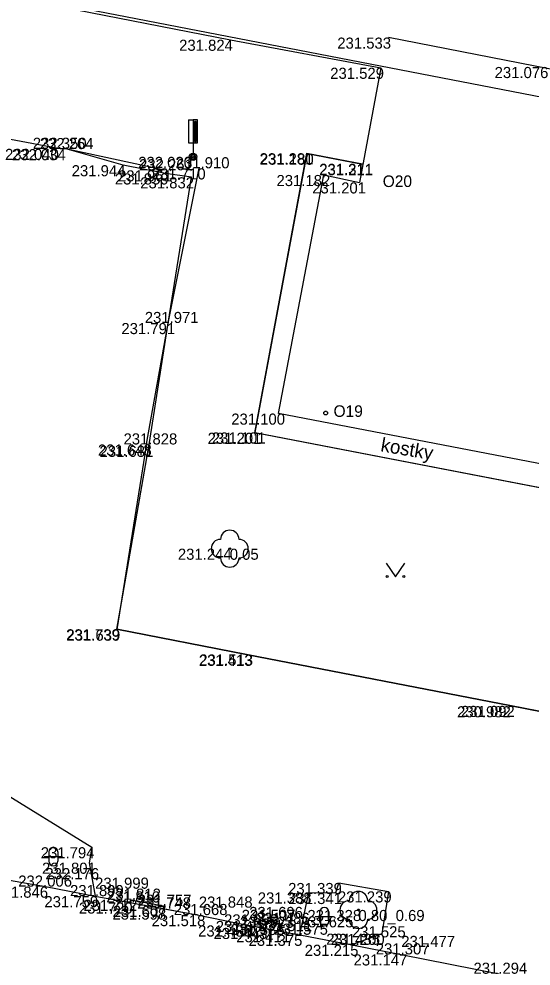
# Model space of a CAD drawing. Extents: x -599516 to -599132, y -1163668 to -1163119.
# Drawn here: x -599461.53 to -599447.72, y -1163158.24 to -1163132.67 of the extents above; entities that cross this region are included whole.
import ezdxf

# ---------------------------------------------------------------- set-up
doc = ezdxf.new("R2010")
doc.units = 0
for name, color, linetype in [('_ZEMERENI OBLAST', 7, 'Continuous'), ('Bod-oznac1', 7, 'Continuous'), ('Bod-oznac2', 7, 'Continuous'), ('Bod-oznac3', 7, 'Continuous'), ('Bod-vyska1', 7, 'Continuous'), ('Bod-vyska2', 7, 'Continuous'), ('Bod-vyska3', 7, 'Continuous'), ('Z_budovy-obvod', 7, 'Continuous'), ('Z_cela-hrobu-dolni-linie', 7, 'Continuous'), ('Z_cela-hrobu-horni-linie', 7, 'Continuous'), ('Z_destove-svody-cislo-foto', 7, 'Continuous'), ('Z_destove-svody-obvod', 7, 'Continuous'), ('Z_komunikace', 7, 'Continuous'), ('Z_kultury-znacky', 7, 'Continuous'), ('Z_nove-stromy-prumer-kmene', 7, 'Continuous'), ('Z_obvod-kmene-spodek-ve-vysce1_2m', 7, 'Continuous'), ('Z_popis-budov-povrchu', 7, 'Continuous'), ('Z_stromy-kere', 7, 'Continuous'), ('Z_stromy-nove-vysazene', 7, 'Continuous'), ('Z_vol-lin-obrubnik', 7, 'Continuous'), ('Z_zdi-ohradni', 7, 'Continuous'), ('Z_znacky-ostatni-orientacni-sloupek', 7, 'Continuous'), ('Z_zpevnene-plochy', 7, 'Continuous')]:
    doc.layers.add(name, color=color, linetype=linetype)

msp = doc.modelspace()

# ---------------------------------------------------------------- linework, layer by layer
at = {"layer": '_ZEMERENI OBLAST'}
msp.add_lwpolyline([(-599246.21, -1163173.61), (-599310.76, -1163161.2), (-599382.471, -1163147.382), (-599418.511, -1163140.298), (-599415.805, -1163126.425), (-599441.73, -1163121.594), (-599445.004, -1163135.25), (-599483.712, -1163127.751), (-599506.25, -1163123.345), (-599510.771, -1163146.476), (-599502.636, -1163301.975), (-599510.038, -1163302.355), (-599510.12, -1163309.17), (-599515.16, -1163309.664), (-599511.204, -1163380.278), (-599506.35, -1163380.56), (-599506.01, -1163391.1), (-599497.946, -1163390.674), (-599491.96, -1163502.01)], dxfattribs=at)
at = {"layer": 'Bod-oznac1'}
for p, q in [((-599451.567, -1163133.168), (-599451.567, -1163133.168)), ((-599455.824, -1163133.226), (-599455.824, -1163133.226)), ((-599451.77, -1163133.983), (-599451.77, -1163133.983)), ((-599460.421, -1163136.173), (-599460.421, -1163136.173)), ((-599460.233, -1163136.181), (-599460.233, -1163136.181)), ((-599456.838, -1163136.389), (-599456.838, -1163136.389)), ((-599453.768, -1163136.291), (-599453.768, -1163136.291)), ((-599453.76, -1163136.303), (-599453.76, -1163136.303)), ((-599458.723, -1163136.614), (-599458.723, -1163136.614)), ((-599457.611, -1163136.753), (-599457.611, -1163136.753)), ((-599456.674, -1163136.699), (-599456.674, -1163136.699)), ((-599452.263, -1163136.586), (-599452.263, -1163136.586)), ((-599452.261, -1163136.576), (-599452.261, -1163136.576)), ((-599457.582, -1163136.836), (-599457.582, -1163136.836)), ((-599456.883, -1163136.941), (-599456.883, -1163136.941)), ((-599453.312, -1163136.879), (-599453.312, -1163136.879)), ((-599452.349, -1163137.078), (-599452.349, -1163137.078)), ((-599457.507, -1163140.877), (-599457.507, -1163140.877)), ((-599454.536, -1163143.322), (-599454.536, -1163143.322)), ((-599455.172, -1163143.84), (-599455.172, -1163143.84)), ((-599455.16, -1163143.832), (-599455.16, -1163143.832)), ((-599458.099, -1163144.192), (-599458.099, -1163144.192)), ((-599458.024, -1163144.157), (-599458.024, -1163144.157)), ((-599455.847, -1163146.971), (-599455.847, -1163146.971)), ((-599458.897, -1163149.157), (-599458.897, -1163149.157)), ((-599458.895, -1163149.147), (-599458.895, -1163149.147)), ((-599455.397, -1163149.836), (-599455.397, -1163149.836)), ((-599455.395, -1163149.826), (-599455.395, -1163149.826)), ((-599448.245, -1163151.226), (-599448.245, -1163151.226)), ((-599448.243, -1163151.216), (-599448.243, -1163151.216)), ((-599459.568, -1163155.034), (-599459.568, -1163155.034)), ((-599459.64, -1163155.451), (-599459.64, -1163155.451)), ((-599460.821, -1163156.098), (-599460.821, -1163156.098)), ((-599452.906, -1163155.999), (-599452.906, -1163155.999)), ((-599459.48, -1163156.355), (-599459.48, -1163156.355)), ((-599458.519, -1163156.452), (-599458.519, -1163156.452)), ((-599453.713, -1163156.254), (-599453.713, -1163156.254)), ((-599452.984, -1163156.269), (-599452.984, -1163156.269)), ((-599451.563, -1163156.226), (-599451.563, -1163156.226)), ((-599458.54, -1163156.526), (-599458.54, -1163156.526)), ((-599457.647, -1163156.689), (-599457.647, -1163156.689)), ((-599457.639, -1163156.615), (-599457.639, -1163156.615)), ((-599456.681, -1163156.866), (-599456.681, -1163156.866)), ((-599452.374, -1163156.728), (-599452.374, -1163156.728)), ((-599455.323, -1163157.146), (-599455.323, -1163157.146)), ((-599454.884, -1163157.212), (-599454.884, -1163157.212)), ((-599454.836, -1163157.024), (-599454.836, -1163157.024)), ((-599454.452, -1163157.105), (-599454.452, -1163157.105)), ((-599454.489, -1163157.301), (-599454.489, -1163157.301)), ((-599453.959, -1163157.398), (-599453.959, -1163157.398)), ((-599451.746, -1163157.373), (-599451.746, -1163157.373)), ((-599452.55, -1163157.668), (-599452.55, -1163157.668)), ((-599451.218, -1163157.928), (-599451.218, -1163157.928))]:
    msp.add_line(p, q, dxfattribs=at)
at = {"layer": 'Bod-oznac2'}
for p, q in [((-599460.421, -1163136.173), (-599460.421, -1163136.173)), ((-599460.233, -1163136.181), (-599460.233, -1163136.181)), ((-599457.611, -1163136.753), (-599457.611, -1163136.753)), ((-599456.674, -1163136.699), (-599456.674, -1163136.699)), ((-599457.507, -1163140.877), (-599457.507, -1163140.877)), ((-599458.024, -1163144.157), (-599458.024, -1163144.157)), ((-599460.821, -1163156.098), (-599460.821, -1163156.098)), ((-599459.48, -1163156.355), (-599459.48, -1163156.355)), ((-599458.519, -1163156.452), (-599458.519, -1163156.452)), ((-599458.54, -1163156.526), (-599458.54, -1163156.526)), ((-599457.647, -1163156.689), (-599457.647, -1163156.689)), ((-599457.639, -1163156.615), (-599457.639, -1163156.615)), ((-599456.681, -1163156.866), (-599456.681, -1163156.866)), ((-599455.323, -1163157.146), (-599455.323, -1163157.146)), ((-599454.884, -1163157.212), (-599454.884, -1163157.212)), ((-599454.836, -1163157.024), (-599454.836, -1163157.024)), ((-599454.452, -1163157.105), (-599454.452, -1163157.105)), ((-599454.489, -1163157.301), (-599454.489, -1163157.301)), ((-599453.959, -1163157.398), (-599453.959, -1163157.398)), ((-599452.55, -1163157.668), (-599452.55, -1163157.668)), ((-599451.218, -1163157.928), (-599451.218, -1163157.928))]:
    msp.add_line(p, q, dxfattribs=at)
at = {"layer": 'Bod-oznac3'}
for p, q in [((-599460.821, -1163156.098), (-599460.821, -1163156.098)), ((-599459.48, -1163156.355), (-599459.48, -1163156.355)), ((-599456.681, -1163156.866), (-599456.681, -1163156.866)), ((-599455.323, -1163157.146), (-599455.323, -1163157.146)), ((-599453.959, -1163157.398), (-599453.959, -1163157.398)), ((-599452.55, -1163157.668), (-599452.55, -1163157.668)), ((-599451.218, -1163157.928), (-599451.218, -1163157.928))]:
    msp.add_line(p, q, dxfattribs=at)
at = {"layer": 'Z_budovy-obvod'}
msp.add_lwpolyline([(-599441.599, -1163138.884), (-599440.699, -1163139.073), (-599440.942, -1163140.393), (-599440.942, -1163140.393), (-599441.039, -1163140.899), (-599441.038, -1163140.9), (-599441.617, -1163143.927), (-599441.618, -1163143.927), (-599441.719, -1163144.457), (-599441.719, -1163144.457), (-599441.951, -1163145.746), (-599454.536, -1163143.322), (-599453.312, -1163136.879), (-599452.349, -1163137.078)], dxfattribs=at)
at = {"layer": 'Z_cela-hrobu-dolni-linie'}
for p, q in [((-599458.54, -1163156.526), (-599457.647, -1163156.689)), ((-599453.959, -1163157.398), (-599452.55, -1163157.668))]:
    msp.add_line(p, q, dxfattribs=at)
for points in [[(-599457.611, -1163136.753), (-599460.233, -1163136.181)], [(-599466.352, -1163155.068), (-599465.003, -1163155.358), (-599463.695, -1163155.552), (-599462.314, -1163155.831), (-599460.821, -1163156.098), (-599459.48, -1163156.355)]]:
    msp.add_lwpolyline(points, dxfattribs=at)
at = {"layer": 'Z_cela-hrobu-horni-linie'}
for points in [[(-599460.421, -1163136.173), (-599463.111, -1163135.666), (-599463.111, -1163135.666), (-599464.381, -1163135.363), (-599464.381, -1163135.363), (-599466.992, -1163134.883), (-599466.992, -1163134.883), (-599469.676, -1163134.264), (-599469.676, -1163134.264), (-599470.948, -1163133.966), (-599470.948, -1163133.966), (-599472.276, -1163133.77), (-599472.276, -1163133.77), (-599474.675, -1163133.29), (-599474.675, -1163133.29), (-599475.999, -1163133.032), (-599476.509, -1163133.063), (-599476.548, -1163133.289), (-599477.916, -1163133.033), (-599477.892, -1163132.869)], [(-599457.611, -1163136.753), (-599460.233, -1163136.181)], [(-599462.314, -1163155.831), (-599460.821, -1163156.098), (-599460.821, -1163156.098), (-599459.48, -1163156.355), (-599459.48, -1163156.355), (-599456.681, -1163156.866), (-599456.681, -1163156.866), (-599455.323, -1163157.146), (-599455.323, -1163157.146), (-599453.959, -1163157.398), (-599453.959, -1163157.398), (-599452.55, -1163157.668), (-599452.55, -1163157.668), (-599451.218, -1163157.928), (-599451.218, -1163157.928), (-599448.581, -1163158.452)]]:
    msp.add_lwpolyline(points, dxfattribs=at)
at = {"layer": 'Z_destove-svody-obvod'}
msp.add_circle((-599453.259, -1163143.308), 0.05, dxfattribs=at)
at = {"layer": 'Z_komunikace'}
msp.add_line((-599458.099, -1163144.192), (-599458.897, -1163149.157), dxfattribs=at)
for points in [[(-599458.099, -1163144.192), (-599457.507, -1163140.877), (-599456.883, -1163136.941), (-599457.582, -1163136.836), (-599458.723, -1163136.614), (-599460.233, -1163136.181), (-599460.421, -1163136.173), (-599463.111, -1163135.666), (-599464.381, -1163135.363), (-599466.992, -1163134.883), (-599469.676, -1163134.264), (-599470.31, -1163134.116), (-599470.376, -1163134.855), (-599470.327, -1163135.489), (-599471.713, -1163135.45), (-599472.484, -1163135.263), (-599472.617, -1163134.911)], [(-599439.001, -1163153.032), (-599448.245, -1163151.226), (-599455.397, -1163149.836), (-599458.897, -1163149.157)], [(-599462.138, -1163153.45), (-599459.568, -1163155.034), (-599459.64, -1163155.451), (-599459.48, -1163156.355), (-599458.54, -1163156.526), (-599458.519, -1163156.452), (-599457.639, -1163156.615), (-599457.647, -1163156.689), (-599456.681, -1163156.866), (-599455.323, -1163157.146), (-599454.884, -1163157.212), (-599454.836, -1163157.024), (-599454.452, -1163157.105), (-599454.489, -1163157.301), (-599453.959, -1163157.398), (-599453.713, -1163156.254), (-599452.984, -1163156.269), (-599452.906, -1163155.999), (-599451.563, -1163156.226), (-599451.746, -1163157.373), (-599452.55, -1163157.668), (-599451.218, -1163157.928), (-599448.581, -1163158.452)]]:
    msp.add_lwpolyline(points, dxfattribs=at)
at = {"layer": 'Z_kultury-znacky'}
for p, q in [((-599451.622, -1163147.36), (-599451.372, -1163147.735)), ((-599451.372, -1163147.735), (-599451.122, -1163147.36)), ((-599460.733, -1163155.161), (-599460.733, -1163155.411)), ((-599460.483, -1163155.161), (-599460.483, -1163155.411)), ((-599460.858, -1163155.286), (-599460.358, -1163155.286)), ((-599453.546, -1163156.908), (-599453.046, -1163156.908)), ((-599453.421, -1163156.783), (-599453.421, -1163157.033)), ((-599453.171, -1163156.783), (-599453.171, -1163157.033))]:
    msp.add_line(p, q, dxfattribs=at)
for centre in [(-599451.597, -1163147.723), (-599451.147, -1163147.723)]:
    msp.add_circle(centre, 0.028, dxfattribs=at)
for centre, start, end in [((-599460.608, -1163155.161), 0, 180), ((-599460.608, -1163155.411), 180, 0), ((-599453.296, -1163156.783), 0, 180), ((-599453.296, -1163157.033), 180, 0)]:
    msp.add_arc(centre, 0.125, start, end, dxfattribs=at)
at = {"layer": 'Z_stromy-kere'}
msp.add_circle((-599452.374, -1163156.728), 0.025, dxfattribs=at)
for centre, start, end in [((-599452.374, -1163156.478), 0, 180), ((-599452.624, -1163156.728), 90, 270), ((-599452.124, -1163156.728), 270, 90), ((-599452.374, -1163156.978), 180, 0)]:
    msp.add_arc(centre, 0.25, start, end, dxfattribs=at)
at = {"layer": 'Z_stromy-nove-vysazene'}
msp.add_circle((-599455.847, -1163146.971), 0.025, dxfattribs=at)
for centre, start, end in [((-599455.847, -1163146.721), 0, 180), ((-599456.097, -1163146.971), 90, 270), ((-599455.597, -1163146.971), 270, 90), ((-599455.847, -1163147.221), 180, 0)]:
    msp.add_arc(centre, 0.25, start, end, dxfattribs=at)
at = {"layer": 'Z_vol-lin-obrubnik'}
for points in [[(-599440.222, -1163146.757), (-599440.971, -1163146.588), (-599455.172, -1163143.84), (-599453.768, -1163136.291), (-599452.261, -1163136.576)], [(-599458.897, -1163149.157), (-599458.024, -1163144.157), (-599457.507, -1163140.877), (-599456.674, -1163136.699)], [(-599458.895, -1163149.147), (-599458.024, -1163144.157), (-599457.507, -1163140.877), (-599456.674, -1163136.699)], [(-599435.992, -1163137.65), (-599439.009, -1163153.02), (-599448.243, -1163151.216), (-599455.395, -1163149.826), (-599458.895, -1163149.147)]]:
    msp.add_lwpolyline(points, dxfattribs=at)
at = {"layer": 'Z_zdi-ohradni'}
msp.add_line((-599451.77, -1163133.983), (-599452.349, -1163137.078), dxfattribs=at)
for points in [[(-599505.31, -1163127.1), (-599505.34, -1163127.084), (-599505.283, -1163126.831), (-599505.275, -1163126.779), (-599504.637, -1163123.757), (-599497.307, -1163125.207), (-599490.955, -1163126.463), (-599484.381, -1163127.728), (-599477.98, -1163128.961), (-599471.642, -1163130.139), (-599463.763, -1163131.675), (-599455.824, -1163133.226), (-599451.77, -1163133.983)], [(-599441.052, -1163135.897), (-599440.936, -1163135.248), (-599451.567, -1163133.168)]]:
    msp.add_lwpolyline(points, dxfattribs=at)
at = {"layer": 'Z_znacky-ostatni-orientacni-sloupek'}
for p, q in [((-599456.963, -1163135.389), (-599456.963, -1163136.014)), ((-599456.963, -1163135.389), (-599456.838, -1163135.389)), ((-599456.963, -1163136.014), (-599456.838, -1163136.014)), ((-599456.838, -1163136.014), (-599456.838, -1163136.289))]:
    msp.add_line(p, q, dxfattribs=at)
for points in [[(-599456.838, -1163136.014), (-599456.713, -1163136.014), (-599456.713, -1163135.389), (-599456.838, -1163135.389)], [(-599456.796, -1163135.971), (-599456.755, -1163135.971), (-599456.755, -1163135.431), (-599456.796, -1163135.431)]]:
    msp.add_lwpolyline(points, close=True, dxfattribs=at)
for radius in [0.1, 0.065, 0.03]:
    msp.add_circle((-599456.838, -1163136.389), radius, dxfattribs=at)
at = {"layer": 'Z_zpevnene-plochy'}
for points in [[(-599455.16, -1163143.832), (-599453.76, -1163136.303), (-599452.263, -1163136.586)], [(-599455.16, -1163143.832), (-599442.067, -1163146.365), (-599440.969, -1163146.578), (-599440.22, -1163146.747), (-599441.337, -1163152.368)], [(-599458.54, -1163156.526), (-599458.519, -1163156.452), (-599457.639, -1163156.615), (-599457.647, -1163156.689)], [(-599454.884, -1163157.212), (-599454.836, -1163157.024), (-599454.452, -1163157.105), (-599454.489, -1163157.301)]]:
    msp.add_lwpolyline(points, dxfattribs=at)

# ---------------------------------------------------------------- texts
at = {"layer": 'Bod-vyska1'}
for s, p in [('231.533', (-599452.945, -1163133.468)), ('231.824', (-599457.213, -1163133.526)), ('231.076', (-599448.7, -1163134.262)), ('231.529', (-599453.136, -1163134.283)), ('232.040', (-599461.91, -1163136.473)), ('232.034', (-599461.724, -1163136.481)), ('232.020', (-599458.316, -1163136.689)), ('231.281', (-599455.042, -1163136.591)), ('231.180', (-599455.032, -1163136.603)), ('231.944', (-599460.112, -1163136.914)), ('231.961', (-599458.862, -1163137.053)), ('231.710', (-599457.948, -1163136.999)), ('231.211', (-599453.433, -1163136.886)), ('231.311', (-599453.431, -1163136.876)), ('231.859', (-599458.948, -1163137.136)), ('231.832', (-599458.261, -1163137.241)), ('231.182', (-599454.586, -1163137.179)), ('231.201', (-599453.621, -1163137.378)), ('231.791', (-599458.771, -1163141.177)), ('231.100', (-599455.806, -1163143.622)), ('231.201', (-599456.444, -1163144.14)), ('231.101', (-599456.328, -1163144.132)), ('231.648', (-599459.402, -1163144.457)), ('231.681', (-599459.361, -1163144.492)), ('231.244', (-599457.247, -1163147.271)), ('231.739', (-599460.263, -1163149.447)), ('231.639', (-599460.252, -1163149.457)), ('231.413', (-599456.682, -1163150.136)), ('231.513', (-599456.669, -1163150.126)), ('230.982', (-599449.713, -1163151.526)), ('231.092', (-599449.607, -1163151.516)), ('231.794', (-599460.947, -1163155.334)), ('231.801', (-599460.912, -1163155.751)), ('231.846', (-599462.199, -1163156.398)), ('231.339', (-599454.272, -1163156.299)), ('231.759', (-599460.848, -1163156.655)), ('231.712', (-599459.794, -1163156.752)), ('231.388', (-599455.091, -1163156.554)), ('231.341', (-599454.269, -1163156.569)), ('231.239', (-599452.929, -1163156.526)), ('231.720', (-599459.918, -1163156.826)), ('231.598', (-599459.013, -1163156.989)), ('231.607', (-599459.005, -1163156.915)), ('231.328', (-599453.752, -1163157.028)), ('231.518', (-599457.955, -1163157.166)), ('231.486', (-599456.701, -1163157.446)), ('231.443', (-599456.284, -1163157.512)), ('231.407', (-599456.225, -1163157.324)), ('231.386', (-599455.818, -1163157.405)), ('231.411', (-599455.67, -1163157.601)), ('231.375', (-599455.338, -1163157.698)), ('231.200', (-599453.12, -1163157.673)), ('231.215', (-599453.824, -1163157.968)), ('231.147', (-599452.505, -1163158.228))]:
    msp.add_text(s, height=0.3, dxfattribs=at).set_placement(p)
at = {"layer": 'Bod-vyska2'}
for s, p in [('232.350', (-599461.161, -1163136.173)), ('232.264', (-599460.974, -1163136.181)), ('232.261', (-599458.294, -1163136.753)), ('231.910', (-599457.304, -1163136.699)), ('231.971', (-599458.139, -1163140.877)), ('231.828', (-599458.713, -1163144.157)), ('232.006', (-599461.554, -1163156.098)), ('231.899', (-599460.157, -1163156.355)), ('231.812', (-599459.156, -1163156.452)), ('231.810', (-599459.176, -1163156.526)), ('231.748', (-599458.342, -1163156.689)), ('231.757', (-599458.33, -1163156.615)), ('231.668', (-599457.358, -1163156.866)), ('231.507', (-599455.525, -1163157.024)), ('231.656', (-599456, -1163157.146)), ('231.523', (-599455.573, -1163157.212)), ('231.486', (-599455.141, -1163157.105)), ('231.511', (-599455.074, -1163157.301)), ('231.575', (-599454.649, -1163157.398)), ('231.435', (-599453.244, -1163157.668)), ('231.307', (-599451.907, -1163157.928)), ('231.294', (-599449.27, -1163158.452))]:
    msp.add_text(s, height=0.3, dxfattribs=at).set_placement(p)
at = {"layer": 'Bod-vyska3'}
for s, p in [('232.176', (-599460.821, -1163155.898)), ('231.999', (-599459.48, -1163156.155)), ('231.848', (-599456.681, -1163156.666)), ('231.696', (-599455.323, -1163156.946)), ('231.625', (-599453.959, -1163157.198)), ('231.525', (-599452.55, -1163157.468)), ('231.477', (-599451.218, -1163157.728))]:
    msp.add_text(s, height=0.3, dxfattribs=at).set_placement(p)
at = {"layer": 'Z_destove-svody-cislo-foto'}
for s, p in [('O20', (-599451.719, -1163137.204)), ('O19', (-599453.046, -1163143.412))]:
    msp.add_text(s, height=0.3125, dxfattribs=at).set_placement(p)
at = {"layer": 'Z_nove-stromy-prumer-kmene'}
msp.add_text('0.05', height=0.3, dxfattribs=at).set_placement((-599455.847, -1163147.271))
at = {"layer": 'Z_obvod-kmene-spodek-ve-vysce1_2m'}
msp.add_text('0.80_0.69', height=0.3, dxfattribs=at).set_placement((-599452.374, -1163157.028))
at = {"layer": 'Z_popis-budov-povrchu'}
msp.add_text('kostky', height=0.375, rotation=350.2145, dxfattribs=at).set_placement((-599451.793, -1163144.338))

doc.saveas('drawing.dxf')
